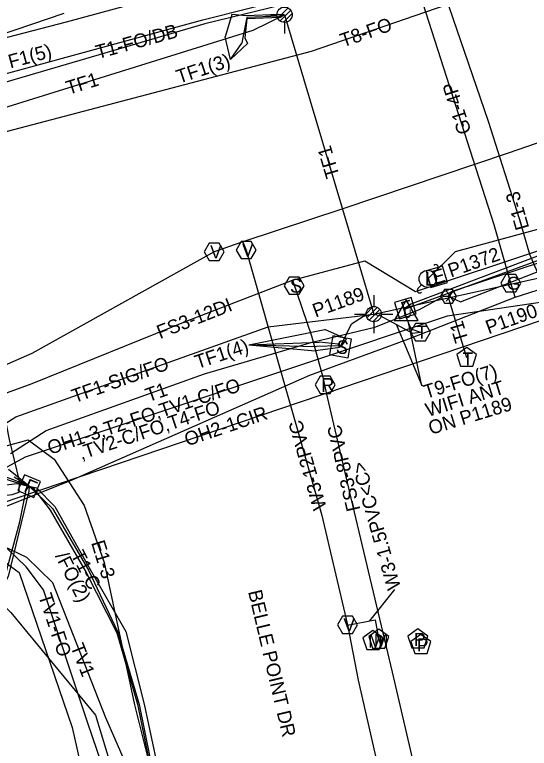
# Model space of a CAD drawing. Extents: x 2336688 to 2352634, y 362473 to 369571.
# Drawn here: x 2351225.4 to 2351374.5, y 368605.1 to 368818 of the extents above; entities that cross this region are included whole.
import ezdxf

# ---------------------------------------------------------------- set-up
doc = ezdxf.new("R2010")
doc.units = 0
for name, color, linetype in [('RD_EX_DV_Prop', 7, 'Continuous'), ('RD_EX_DV_TX_Prop', 7, 'Continuous'), ('RD_EX_RW', 7, 'Continuous'), ('RD_EX_RW_TX', 7, 'Continuous'), ('RD_HC_CL_Rel', 7, 'Continuous'), ('RD_HC_Data_Tic', 7, 'Continuous'), ('RD_PD_CstnLmt', 7, 'Continuous'), ('RD_PD_Final_TrvlWay', 7, 'Continuous'), ('RD_PD_FOC', 7, 'Continuous'), ('RD_PD_PatLn2', 7, 'Continuous'), ('RD_PD_PatLn3', 7, 'Continuous'), ('RD_PD_PatLn4', 7, 'Continuous'), ('RD_SHT_ShtClip', 7, 'Continuous'), ('RD_Sketch1', 7, 'Continuous'), ('RD_Sketch2', 7, 'Continuous'), ('RD_Sketch5', 7, 'Continuous'), ('RD_Sketch8', 7, 'Continuous'), ('RD_TX_Misc1', 7, 'Continuous')]:
    doc.layers.add(name, color=color, linetype=linetype)

msp = doc.modelspace()

# ---------------------------------------------------------------- linework, layer by layer
at = {"layer": 'RD_EX_RW'}
for p, q in [((2351343.39, 368710.32), (2351339.44, 368728.67)), ((2351335.89, 368728.17), (2351343.35, 368710.33))]:
    msp.add_line(p, q, dxfattribs=at)
at = {"layer": 'RD_EX_RW_TX'}
for points in [[(2351026.67, 368705.73), (2351072.69, 368726.31), (2351095.34, 368740.06), (2351116.22, 368749.97), (2351165.51, 368767.17), (2351212.21, 368781.21), (2351311.35, 368807.4), (2351356.55, 368822.99), (2351403.13, 368840.09), (2351451.54, 368852.43), (2351499.93, 368866.02), (2351548.68, 368876.43), (2351597.38, 368889.51), (2351644.05, 368904.92), (2351693.91, 368918.56), (2351742.3, 368929.46), (2351791.99, 368937.8), (2351833.59, 368947.12), (2351885, 368956.88), (2351939.56, 368969.89)], [(2351765.09, 368961.33), (2351762.65, 368958.7), (2351731.46, 368952.33), (2351690.92, 368936.8), (2351644.39, 368912.81), (2351617.15, 368901.31), (2351597.28, 368893.86), (2351548.04, 368883.26), (2351498.82, 368871.39), (2351450.63, 368858.65), (2351402.34, 368844.85), (2351353.62, 368832.17), (2351306.23, 368821.59), (2351280.49, 368815.25), (2351211.24, 368794.97), (2351186.06, 368787.7), (2351186.43, 368794.28), (2351186.89, 368796.09), (2351185.08, 368794.48), (2351153.67, 368786.02), (2351107.67, 368770.53), (2351057.77, 368748.3), (2351012.48, 368735.27)], [(2351011.06, 368741.96), (2351053.69, 368758.05), (2351107.39, 368776.15), (2351152.93, 368787.71), (2351184.57, 368795.27), (2351186.89, 368796.09), (2351188.61, 368798.02), (2351216.11, 368809.61), (2351240.4, 368815.83), (2351267.18, 368823.24), (2351289.83, 368828.63), (2351291.64, 368830.61), (2351292.6, 368830.98), (2351299.9, 368833.16), (2351351.82, 368850.12), (2351397.43, 368865.04), (2351441.13, 368877.68), (2351493.72, 368892.16)], [(2351012.91, 368733.98), (2351058.97, 368746.67), (2351108.07, 368769.44), (2351156.12, 368783.52), (2351185.09, 368789.77), (2351211.25, 368797.72), (2351279.85, 368816.48), (2351306.31, 368823.22), (2351353.2, 368834.25), (2351401.27, 368847.29), (2351450, 368860.64), (2351498.06, 368873.82)], [(2351499.06, 368872), (2351450.2, 368859.78), (2351401.85, 368845.93), (2351353.7, 368831.58), (2351326.67, 368826.28), (2351311.23, 368827.61), (2351289.86, 368835.15), (2351289.09, 368835.13), (2351287.25, 368834.26), (2351261.79, 368833.03), (2351237.29, 368828.25), (2351212.6, 368822.12), (2351203.83, 368819.92), (2351199.75, 368821.32), (2351198.76, 368823.01), (2351199.15, 368820.41), (2351205.9, 368785.94), (2351223.8, 368694.72), (2351226.67, 368682.68), (2351226.54, 368679.35), (2351224.55, 368678.69), (2351202.58, 368675.7), (2351201.7, 368675.07)], [(2351356.36, 368718.44), (2351351.37, 368734.97), (2351351.07, 368736.27), (2351352.08, 368735.83), (2351354.55, 368734.64), (2351363.44, 368738.12), (2351379.73, 368744.54), (2351398.33, 368751.76), (2351424.73, 368759.16), (2351470.85, 368771.57), (2351519.59, 368782.94), (2351559.62, 368792.7), (2351576.11, 368797.45), (2351601.1, 368804.55), (2351618.26, 368808.83), (2351664.35, 368818.5), (2351712.26, 368827.78), (2351760.99, 368838.04), (2351806.87, 368848.05), (2351854.2, 368855.12), (2351907.65, 368859.27)], [(2351135.8, 368572), (2351173.22, 368600.21), (2351189.77, 368614.34), (2351210.63, 368632.56), (2351222.68, 368655.41), (2351226.83, 368670.78), (2351228.71, 368679.98), (2351229.57, 368681.2), (2351225.04, 368683.05), (2351211.34, 368687.86), (2351203.12, 368694.09), (2351169.59, 368777.93), (2351174.2, 368783.35), (2351185.48, 368794.16), (2351186.89, 368796.09), (2351188.51, 368798.16), (2351216, 368810.33), (2351239.68, 368818.38)], [(2351186.89, 368796.09), (2351185.12, 368794.04), (2351173.71, 368783.8), (2351168.72, 368777.97), (2351171.2, 368768.56), (2351202.54, 368693.87), (2351211.04, 368687.24), (2351224.67, 368682.6), (2351229.57, 368681.2), (2351231.17, 368680), (2351235.69, 368674.21), (2351246.1, 368656.13), (2351254.95, 368638.6), (2351260.98, 368617.88), (2351272.14, 368562.89), (2351276.08, 368537.07), (2351277.56, 368512.26), (2351278.05, 368486.96)], [(2351224.12, 368690.62), (2351234.5, 368697.35), (2351280.33, 368713.75), (2351311.59, 368722.97), (2351329.76, 368727.3), (2351342.71, 368732.42), (2351349.68, 368736.29), (2351351.07, 368736.27), (2351351.49, 368736.8), (2351351.97, 368737.62), (2351379.15, 368746.62), (2351398.04, 368753.27), (2351424.06, 368760.88), (2351469.79, 368774.45), (2351518.56, 368788.63)], [(2351439.98, 368755.4), (2351440.09, 368752.96), (2351439.42, 368751.44), (2351426.58, 368748.77), (2351413.32, 368749.23), (2351393.05, 368750.66), (2351379.19, 368747.38), (2351340.4, 368733.21), (2351338.54, 368732.83), (2351338.37, 368731.29), (2351340.19, 368726.85), (2351342.99, 368725.87)], [(2351439.98, 368755.4), (2351439.65, 368752.9), (2351439.11, 368752.31), (2351426.3, 368749.79), (2351413.18, 368749.92), (2351393.14, 368751.78), (2351378.88, 368748.66), (2351340.14, 368734.01), (2351338.54, 368732.83)], [(2351329.41, 368731.07), (2351331.19, 368730.71), (2351340.65, 368725.59), (2351342.99, 368725.87)], [(2351225.25, 368683.92), (2351229.57, 368681.2), (2351227.64, 368682.72), (2351223.6, 368685.96)], [(2351004.61, 368611.63), (2351052.31, 368628.22), (2351065.52, 368632.64), (2351077.77, 368640.55), (2351101.18, 368650.98), (2351144.83, 368666.46), (2351192.1, 368678.05), (2351206.58, 368679.48), (2351225.97, 368681.99), (2351229.57, 368681.2)], [(2351229.57, 368681.2), (2351229.44, 368679.68), (2351227.29, 368670.49), (2351223.43, 368655), (2351211.17, 368632.5), (2351190.26, 368614.07), (2351173.25, 368599.65), (2351136.04, 368571.66)], [(2351229.57, 368681.2), (2351236.31, 368674.67), (2351246.71, 368656.78), (2351255.29, 368638.83), (2351261.43, 368617.85), (2351272.66, 368562.38), (2351276.62, 368537.07), (2351278.06, 368512.39), (2351278.47, 368487.08), (2351283.79, 368461.87), (2351287.88, 368443.56), (2351293.65, 368423.89), (2351294.69, 368421.28), (2351294.65, 368418.28), (2351299.27, 368384.69), (2351302.21, 368366.6), (2351314.15, 368317.48), (2351323.5, 368283.26), (2351324.62, 368280.4), (2351326.65, 368268.48), (2351332.74, 368242.9), (2351338.8, 368220.39)], [(2351229.57, 368681.2), (2351231.65, 368680.73), (2351237.02, 368675.27), (2351247.28, 368656.99), (2351257.55, 368638.99), (2351262.92, 368617.91), (2351274.68, 368562.58), (2351277.55, 368537.01), (2351278.86, 368512.21), (2351279.63, 368487.33), (2351285.21, 368461.97), (2351288.7, 368443.65), (2351294.43, 368424.15), (2351294.69, 368421.28), (2351295.38, 368418.33), (2351300.74, 368384.8), (2351303.48, 368366.6), (2351315.5, 368317.48), (2351324.47, 368283.48), (2351324.62, 368280.4), (2351326.05, 368278.31), (2351327.76, 368268.72), (2351334.33, 368243.44), (2351340.43, 368220.68)], [(2351201.7, 368675.07), (2351200.9, 368674.18), (2351199.85, 368669.59), (2351200.94, 368667.75), (2351209.33, 368659.77), (2351224.28, 368644.55), (2351248.82, 368614.72), (2351260.32, 368576.83), (2351263.86, 368573.06), (2351274.91, 368568.76), (2351278.23, 368562.48), (2351287.8, 368513.68), (2351294.26, 368490.16), (2351304.11, 368465.66), (2351324.92, 368418.83), (2351336.62, 368371.25), (2351345.89, 368322.07), (2351357.63, 368274.06), (2351367.51, 368226.74)], [(2351201.7, 368675.07), (2351202.6, 368674.93), (2351203.83, 368673.26), (2351214.84, 368664.62), (2351226.69, 368656.09), (2351242.04, 368611.12), (2351265.35, 368507.38), (2351270.72, 368482.62), (2351280.89, 368442.69), (2351294.4, 368382.92), (2351309.3, 368316.16), (2351323.01, 368267.6), (2351333.96, 368219.65)], [(2351347.88, 368220.89), (2351335.42, 368269.54), (2351319.4, 368317.47), (2351304.95, 368385.45), (2351291.9, 368443.88), (2351282.94, 368489.45), (2351270.28, 368536), (2351260.61, 368560.04), (2351253.62, 368591.72), (2351246.42, 368612.74), (2351233.68, 368651.1), (2351228.65, 368657.79), (2351212.63, 368673.18), (2351209.05, 368673.77), (2351206.87, 368673.76), (2351205.08, 368675.04), (2351201.7, 368675.07)], [(2351106.98, 368642.54), (2351108.2, 368643.82), (2351112.1, 368647.52), (2351122.3, 368650.08), (2351147.51, 368660.33), (2351168.99, 368663.71), (2351196.81, 368668.47), (2351215.57, 368666.89), (2351228.74, 368660.6), (2351236.29, 368653.23), (2351251.67, 368614.06), (2351260.37, 368594.17), (2351276.84, 368580.47), (2351283.03, 368563.52), (2351295.62, 368515.94), (2351309.17, 368467.12), (2351318.82, 368418.4), (2351327.99, 368370.54), (2351340.14, 368321.05), (2351349.7, 368273.01), (2351349.03, 368263.4), (2351348.72, 368262.22), (2351350.42, 368262.16), (2351361.39, 368225.88)]]:
    msp.add_lwpolyline(points, dxfattribs=at)
for points in [[(2351353.38, 368736.27), (2351352.22, 368738.26), (2351349.91, 368738.26), (2351348.76, 368736.27), (2351349.91, 368734.27), (2351352.22, 368734.27)], [(2351340.21, 368735.94), (2351335.43, 368734.49), (2351336.88, 368729.71), (2351341.66, 368731.16)], [(2351345.87, 368725.87), (2351344.43, 368728.37), (2351341.54, 368728.37), (2351340.1, 368725.87), (2351341.54, 368723.37), (2351344.43, 368723.37)], [(2351356.36, 368721.44), (2351353.51, 368719.37), (2351354.6, 368716.01), (2351358.13, 368716.01), (2351359.22, 368719.37)], [(2351232.84, 368682.52), (2351228.24, 368684.47), (2351226.29, 368679.87), (2351230.9, 368677.92)]]:
    msp.add_lwpolyline(points, close=True, dxfattribs=at)
at = {"layer": 'RD_HC_CL_Rel'}
for points in [[(2351370.43, 368735.99), (2351369.13, 368740.04), (2351364.33, 368757), (2351341.1, 368829.3), (2351336.77, 368841.59)], [(2351006.87, 368605.31), (2351056.9, 368620.23), (2351109.19, 368634.4), (2351152.1, 368649.14), (2351197.21, 368665.27), (2351219.2, 368673.88), (2351241.79, 368682.94), (2351310.92, 368713.38), (2351339.57, 368723.87), (2351370.43, 368735.99), (2351381.33, 368739.5), (2351410.08, 368748.57), (2351425.39, 368754.01), (2351470.14, 368766.16), (2351521.03, 368777.02)]]:
    msp.add_lwpolyline(points, dxfattribs=at)
msp.add_lwpolyline([(2351370.58, 368737.54), (2351372.02, 368740.04), (2351370.58, 368742.54), (2351367.69, 368742.54), (2351366.25, 368740.04), (2351367.69, 368737.54)], close=True, dxfattribs=at)
at = {"layer": 'RD_HC_Data_Tic'}
for p, q in [((2351301.61, 368816.92), (2351304.6, 368819.91)), ((2351302.27, 368816.16), (2351305.36, 368819.26)), ((2351303.27, 368815.76), (2351305.77, 368818.25)), ((2351298.04, 368817.94), (2351301.36, 368817.95)), ((2351303.57, 368815.74), (2351303.57, 368812.45)), ((2351346.83, 368743.08), (2351347.89, 368744.15)), ((2351342.23, 368738.49), (2351343.3, 368739.55)), ((2351329.41, 368736.57), (2351329.41, 368733.29)), ((2351327.19, 368731.2), (2351329.28, 368733.28)), ((2351327.45, 368730.04), (2351330.44, 368733.03)), ((2351323.88, 368731.06), (2351327.19, 368731.07)), ((2351328.1, 368729.28), (2351331.2, 368732.38)), ((2351329.11, 368728.87), (2351331.6, 368731.37)), ((2351331.62, 368731.07), (2351334.94, 368731.08)), ((2351329.41, 368728.85), (2351329.41, 368725.57))]:
    msp.add_line(p, q, dxfattribs=at)
for centre, radius in [((2351303.57, 368817.95), 2.22), ((2351345.06, 368741.32), 2.5), ((2351329.41, 368731.07), 2.22)]:
    msp.add_circle(centre, radius, dxfattribs=at)
for centre, start, end in [((2351347.36, 368744.68), 315, 135), ((2351342.76, 368737.96), 135, 315)]:
    msp.add_arc(centre, 0.75, start, end, dxfattribs=at)
at = {"layer": 'RD_PD_CstnLmt'}
msp.add_line((2351335.38, 368651.2), (2351328.14, 368642.08), dxfattribs=at)
at = {"layer": 'RD_PD_Final_TrvlWay'}
for points in [[(2351380.9, 368735.05), (2351380.01, 368735.9), (2351374.68, 368748.33), (2351371.69, 368758.73), (2351362.67, 368786.92), (2351350.13, 368823.67), (2351348.41, 368830.89), (2351338.9, 368853.84), (2351332.14, 368881.62), (2351334.27, 368886.55), (2351349.44, 368892.24), (2351390.85, 368902), (2351422.65, 368909.4), (2351429.43, 368916.53), (2351427.53, 368923.8)], [(2351962.19, 368868.54), (2351879.61, 368860.3), (2351872.73, 368864.24), (2351807.16, 368856.02), (2351766.5, 368848.48), (2351760.54, 368842.85), (2351755.71, 368847.01), (2351656.05, 368826.47), (2351653.74, 368820.38), (2351649.2, 368824.53), (2351583.65, 368809.05), (2351587.65, 368792.13), (2351587.61, 368789.27), (2351586.29, 368791.8), (2351582.29, 368808.73), (2351542.35, 368799.3), (2351537.51, 368798.37), (2351536.49, 368793.38), (2351533.02, 368797.4), (2351459.1, 368778.67), (2351456.43, 368773.13), (2351451.34, 368775.83), (2351353, 368749.17), (2351345.06, 368741.32)], [(2351201.7, 368675.07), (2351203.2, 368677.17), (2351207.26, 368685.59), (2351212.59, 368690.14), (2351215.83, 368690.95), (2351229.23, 368694.57), (2351236.84, 368689.03), (2351245.47, 368675.57), (2351251.27, 368659.04), (2351260.11, 368617.75), (2351265.77, 368594.9), (2351274.15, 368562.38), (2351274.64, 368537), (2351280.71, 368512.32), (2351305.52, 368419.51), (2351311.8, 368373.58), (2351328.95, 368318.81), (2351342.04, 368267.45), (2351345.25, 368254.66), (2351349.65, 368254.61), (2351400.34, 368234.37), (2351420.6, 368224.79), (2351424.74, 368222.21)]]:
    msp.add_lwpolyline(points, dxfattribs=at)
msp.add_lwpolyline([(2351349.38, 368745.01), (2351344.57, 368743.62), (2351345.96, 368738.82), (2351350.77, 368740.21)], close=True, dxfattribs=at)
at = {"layer": 'RD_PD_FOC'}
for p, q in [((2351287.91, 368804.99), (2351286.36, 368811.48)), ((2351287.91, 368804.99), (2351291.19, 368809.73)), ((2351287.91, 368804.99), (2351292.86, 368809.61)), ((2351293.24, 368722.21), (2351315.27, 368726.64)), ((2351293.24, 368722.21), (2351313.58, 368722.97)), ((2351293.24, 368722.21), (2351312.87, 368721.72)), ((2351293.24, 368722.21), (2351312.45, 368720.41))]:
    msp.add_line(p, q, dxfattribs=at)
at = {"layer": 'RD_PD_PatLn3'}
msp.add_lwpolyline([(2351338.82, 368735.2), (2351335.35, 368729.2), (2351342.28, 368729.2)], close=True, dxfattribs=at)
at = {"layer": 'RD_SHT_ShtClip'}
for p, q in [((2351303.57, 368817.95), (2351329.41, 368731.07)), ((2351329.41, 368731.07), (2351439.98, 368755.4))]:
    msp.add_line(p, q, dxfattribs=at)
for points in [[(2351185.13, 368781.1), (2351195.16, 368782.52), (2351294.51, 368813.43), (2351303.57, 368817.95)], [(2351069.24, 368629.63), (2351099.2, 368634.72), (2351413.11, 368741.21), (2351439.98, 368755.4)], [(2351201.7, 368675.07), (2351228.45, 368689.67), (2351350.75, 368730.61), (2351380.9, 368735.05)], [(2351199.73, 368684.73), (2351225.68, 368701.28), (2351298.85, 368727.43), (2351329.41, 368731.07)]]:
    msp.add_lwpolyline(points, dxfattribs=at)
at = {"layer": 'RD_Sketch2'}
for points in [[(2351897.87, 368918.99), (2351839.37, 368906.5), (2351797.47, 368896.96), (2351751.8, 368884.48), (2351707.52, 368870.2), (2351656.24, 368856.32), (2351608.11, 368843.77), (2351558.65, 368832.09), (2351508.67, 368819.53), (2351459.49, 368806.33), (2351412.81, 368793.12), (2351368.32, 368777.82), (2351320.48, 368761.6), (2351291.49, 368752.07), (2351283.21, 368749.13), (2351230.34, 368719.64), (2351184.82, 368699.7), (2351136.28, 368683.67), (2351113.69, 368676.51), (2351093.58, 368668.35), (2351042.86, 368655.18), (2350995.25, 368636.19)], [(2351291.49, 368752.07), (2351292.44, 368749.67), (2351314.26, 368673.05), (2351321.83, 368640.92), (2351324.93, 368624.92), (2351336.6, 368573.65), (2351350, 368517.73), (2351358.62, 368479.99), (2351360.92, 368468.8), (2351364.7, 368449.04), (2351381.15, 368378.14), (2351391.51, 368333.08), (2351400.94, 368286.23), (2351402.7, 368272.49), (2351407.94, 368235.33)], [(2351291.49, 368752.07), (2351292.44, 368749.67), (2351314.26, 368673.05), (2351321.83, 368640.92), (2351324.93, 368624.92), (2351336.6, 368573.65), (2351350, 368517.73), (2351358.62, 368479.99), (2351360.92, 368468.8), (2351364.7, 368449.04), (2351381.15, 368378.14), (2351391.51, 368333.08), (2351400.94, 368286.23), (2351402.7, 368272.49), (2351407.94, 368235.33)], [(2351321.85, 368640.86), (2351329.78, 368642.39), (2351330.82, 368637.05)]]:
    msp.add_lwpolyline(points, dxfattribs=at)
for points in [[(2351295.33, 368749.67), (2351293.89, 368752.17), (2351291, 368752.17), (2351289.56, 368749.67), (2351291, 368747.17), (2351293.89, 368747.17)], [(2351286.09, 368749.13), (2351284.65, 368751.63), (2351281.76, 368751.63), (2351280.32, 368749.13), (2351281.76, 368746.63), (2351284.65, 368746.63)], [(2351324.72, 368640.92), (2351323.28, 368643.42), (2351320.39, 368643.42), (2351318.95, 368640.92), (2351320.39, 368638.42), (2351323.28, 368638.42)], [(2351329.19, 368639.31), (2351326.29, 368637.2), (2351327.4, 368633.79), (2351330.98, 368633.79), (2351332.09, 368637.2)], [(2351330.85, 368639.65), (2351327.95, 368637.54), (2351329.05, 368634.13), (2351332.64, 368634.13), (2351333.75, 368637.54)], [(2351342.23, 368639.76), (2351339.33, 368637.66), (2351340.44, 368634.25), (2351344.02, 368634.25), (2351345.13, 368637.66)], [(2351343.08, 368638.18), (2351340.18, 368636.07), (2351341.29, 368632.66), (2351344.87, 368632.66), (2351345.98, 368636.07)]]:
    msp.add_lwpolyline(points, close=True, dxfattribs=at)
at = {"layer": 'RD_Sketch5'}
for points in [[(2350997.52, 368629.24), (2351044.06, 368648.74), (2351094.71, 368664.43), (2351137.99, 368678.97), (2351178.36, 368692), (2351230.47, 368710.98), (2351275.34, 368729.17), (2351305.9, 368740.94), (2351326.85, 368746.53), (2351341.51, 368737.66), (2351378.42, 368749.96), (2351394.31, 368753.99), (2351397.31, 368754.91), (2351423.69, 368762.34), (2351470.05, 368773.88), (2351518.77, 368787.72)], [(2351305.9, 368740.94), (2351311.36, 368724.83), (2351314.62, 368712.79), (2351315.62, 368708.28), (2351322.75, 368677.68), (2351334.79, 368627.22), (2351346.13, 368578.21), (2351355.63, 368530.54), (2351360.98, 368478.66), (2351359.66, 368472.12), (2351358.04, 368464.88), (2351357.27, 368450.93), (2351360.12, 368432.44), (2351372.24, 368377.88), (2351381.74, 368331.13), (2351394.45, 368282.37), (2351406.13, 368234.27)]]:
    msp.add_lwpolyline(points, dxfattribs=at)
for points in [[(2351309.24, 368739.33), (2351307.79, 368741.83), (2351304.9, 368741.83), (2351303.46, 368739.33), (2351304.9, 368736.83), (2351307.79, 368736.83)], [(2351318.25, 368710.53), (2351316.8, 368713.04), (2351313.91, 368713.04), (2351312.47, 368710.53), (2351313.91, 368708.03), (2351316.8, 368708.03)]]:
    msp.add_lwpolyline(points, close=True, dxfattribs=at)
at = {"layer": 'RD_Sketch8'}
for points in [[(2351303.57, 368817.95), (2351301.77, 368818), (2351292.47, 368817.64), (2351288.25, 368818.02), (2351286.36, 368811.48)], [(2351303.57, 368817.95), (2351301.92, 368817.52), (2351292.63, 368817.17), (2351291.5, 368811.33), (2351291.19, 368809.73)], [(2351303.57, 368817.95), (2351302.27, 368817.1), (2351292.6, 368816.73), (2351292.01, 368811.26), (2351292.86, 368809.61)], [(2351319.78, 368721.58), (2351320.14, 368722.44), (2351322.97, 368728.25), (2351326.48, 368730.48), (2351328.51, 368730.96), (2351329.41, 368731.07)], [(2351319.78, 368721.58), (2351320.38, 368722.2), (2351321.51, 368723.82), (2351315.27, 368726.64)], [(2351319.78, 368721.58), (2351319.11, 368722.34), (2351313.58, 368722.97)], [(2351319.78, 368721.58), (2351319.02, 368721.28), (2351312.45, 368720.41)], [(2351319.78, 368721.58), (2351319.1, 368721.86), (2351312.87, 368721.72)]]:
    msp.add_lwpolyline(points, dxfattribs=at)
msp.add_lwpolyline([(2351322.96, 368723.83), (2351317.54, 368724.76), (2351316.61, 368719.34), (2351322.03, 368718.41)], close=True, dxfattribs=at)

# ---------------------------------------------------------------- texts
at = {"layer": 'RD_EX_DV_Prop'}
for rotation, p in [(106.045, (2351374.51, 368756.16)), (286.8851, (2351247.49, 368664.78))]:
    msp.add_text('E1-3', height=4, rotation=rotation, dxfattribs=at).set_placement(p)
at = {"layer": 'RD_EX_DV_TX_Prop'}
for s, rotation, p in [('P1372', 19.5513, (2351351.79, 368741.68)), ('P1189', 19.9486, (2351312.55, 368730.05)), ('P1190', 19.9486, (2351362.71, 368725.21))]:
    msp.add_text(s, height=4, rotation=rotation, dxfattribs=at).set_placement(p)
at = {"layer": 'RD_EX_RW'}
for s, rotation, p in [('T8-FO', 19.0262, (2351320.49, 368808.44)), ('T1-FO/DB', 15.2972, (2351249.47, 368805.06)), ('T1', 106.8152, (2351356.92, 368723.5)), ('T9-FO(7)', 17.0186, (2351344.56, 368706.49)), ('WIFI ANT', 17.0186, (2351345.15, 368701.23)), ('T1', 19.6871, (2351264.14, 368705.52)), ('ON P1189', 17.0186, (2351345.98, 368696.04)), ('T1-C', 296.77, (2351241.58, 368661.34)), ('/FO(2)', 296.77, (2351237.02, 368660.87)), ('TV1-FO', 288.3682, (2351232.15, 368649.35)), ('TV1', 291.4323, (2351241.44, 368634.64))]:
    msp.add_text(s, height=4, rotation=rotation, dxfattribs=at).set_placement(p)
at = {"layer": 'RD_EX_RW_TX'}
for s, height, p in [('X', 3, (2351350.12, 368734.77)), ('T', 3.75, (2351341.78, 368723.99)), ('T', 3.75, (2351355.13, 368716.21))]:
    msp.add_text(s, height=height, dxfattribs=at).set_placement(p)
for rotation, p in [(16.9079, (2351338.04, 368730.58)), (337.0778, (2351227.75, 368679.79))]:
    msp.add_text('F', height=4, rotation=rotation, dxfattribs=at).set_placement(p)
at = {"layer": 'RD_HC_CL_Rel'}
msp.add_text('G', height=3.75, dxfattribs=at).set_placement((2351367.98, 368738.17))
at = {"layer": 'RD_HC_Data_Tic'}
msp.add_text('L', height=4, rotation=360, dxfattribs=at).set_placement((2351344.25, 368739.38))
at = {"layer": 'RD_PD_CstnLmt'}
for s, p in [('W3-12PVC', (2351315.81, 368674.91)), ('W3-1.5PVC<C>', (2351337.31, 368651.75))]:
    msp.add_text(s, height=4, rotation=105.8961, dxfattribs=at).set_placement(p)
at = {"layer": 'RD_PD_Final_TrvlWay'}
msp.add_text('E', height=4, rotation=16.126, dxfattribs=at).set_placement((2351347.06, 368739.66))
at = {"layer": 'RD_PD_FOC'}
for s, rotation, p in [('TF1(5)', 15.2972, (2351220.97, 368801.46)), ('TF1(3)', 18.4374, (2351272.99, 368797.91)), ('TF1(4)', 18.4374, (2351278.33, 368715.13))]:
    msp.add_text(s, height=4, rotation=rotation, dxfattribs=at).set_placement(p)
at = {"layer": 'RD_PD_PatLn2'}
msp.add_text('G1-4P', height=4, rotation=107.8043, dxfattribs=at).set_placement((2351357.76, 368783.98))
at = {"layer": 'RD_PD_PatLn3'}
msp.add_text('U', height=2.4, dxfattribs=at).set_placement((2351338.06, 368730))
at = {"layer": 'RD_PD_PatLn4'}
for s, rotation, p in [('TF1', 17.2813, (2351240.98, 368794.68)), ('TF1', 106.5605, (2351319.56, 368771.2)), ('TF1-SIG/FO', 19.6992, (2351242.73, 368705.24)), ('OH1-3,T2-FO,TV1-C/FO', 18.5052, (2351235.64, 368690.25)), (',TV2-C/FO,T4-FO', 18.5052, (2351244.68, 368688.76)), ('OH2-1CIR', 18.7395, (2351275.37, 368692.7))]:
    msp.add_text(s, height=4, rotation=rotation, dxfattribs=at).set_placement(p)
at = {"layer": 'RD_Sketch1'}
for s, rotation, p in [('FS3-12DI', 21.4543, (2351267.48, 368723.82)), ('FS3-8PVC', 103.1249, (2351325.57, 368674.38))]:
    msp.add_text(s, height=4, rotation=rotation, dxfattribs=at).set_placement(p)
at = {"layer": 'RD_Sketch2'}
for s, p in [('V', (2351282, 368747.25)), ('V', (2351291.23, 368747.79)), ('V', (2351320.62, 368639.04)), ('M', (2351327.82, 368634.27)), ('M', (2351329.48, 368634.61))]:
    msp.add_text(s, height=3.75, dxfattribs=at).set_placement(p)
for p in [(2351341.08, 368634.84), (2351341.93, 368633.26)]:
    msp.add_text('P', height=3.75, rotation=360, dxfattribs=at).set_placement(p)
at = {"layer": 'RD_Sketch5'}
for s, p in [('S', (2351305.12, 368737.33)), ('R', (2351314.13, 368708.53))]:
    msp.add_text(s, height=4, dxfattribs=at).set_placement(p)
at = {"layer": 'RD_Sketch8'}
msp.add_text('S', height=3.89, rotation=350.2605, dxfattribs=at).set_placement((2351318.28, 368719.87))
at = {"layer": 'RD_TX_Misc1'}
msp.add_text('BELLE POINT DR', height=4, rotation=283.3145, dxfattribs=at).set_placement((2351292.98, 368650.57))

doc.saveas('drawing.dxf')
